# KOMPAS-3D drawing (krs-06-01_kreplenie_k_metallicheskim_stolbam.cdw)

Views: Спереди 1, Проекционный вид 3, Вид 4
Referenced files: Крон.cdw
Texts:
  КРC-06-01
  Крепление к  металлическим столбам
  Никита
  Комплектность
  крепления к столбам
  Гайка М8
  Адаптер
  Хомут
  под любой   трубы
  любой размер
  Изготавливаем комплекты крепления к металлическим столбам
  (адаптеры крепления на столб) по стандартным чертежам, а также
  по вашим размерам.
  Покрытие: Порошковая покраска / Ц6хр / Горячее цинкование.
  POLYLINE_STYLE_0.18_RGB_0_0_0
  ООО "Центр инженерных
  услуг "МОДЕЛЬЕР"
  Крепление к
  металлическим столбам
Dimensions and other numbers on the sheet: 1:4; 2 шт.; 1 шт.; 118; 15; 30; 9; 138; 32,5; 6,5; 4 отв.; 110; 70; 2,5; 130; 1:2; 2216.01.00.003-; 1; 0; 2; 3; 4; 5; 6; 7; 8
